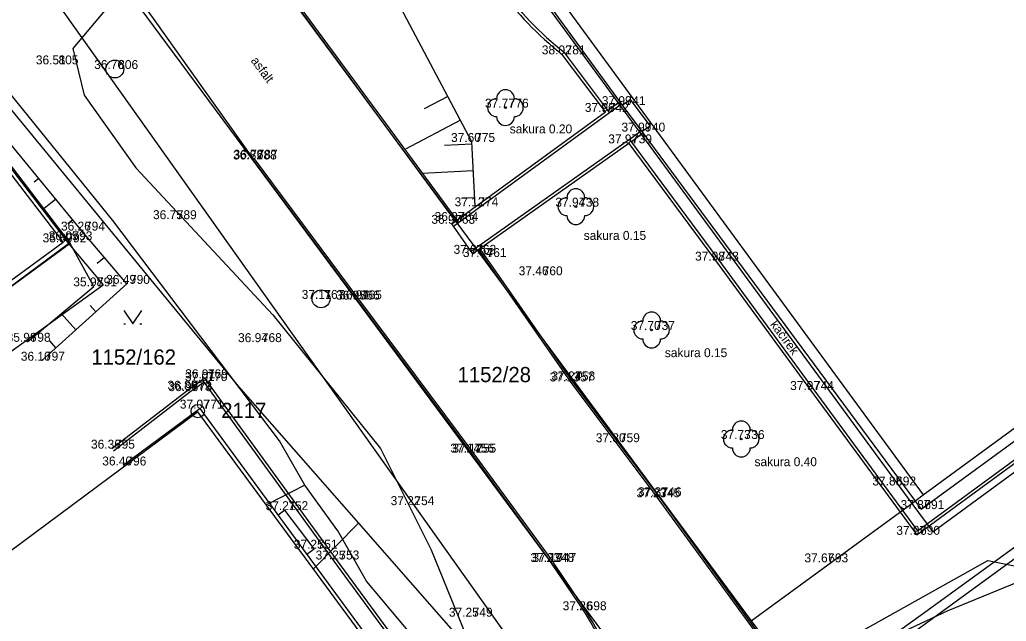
# Model space of a CAD drawing. Extents: x -609709 to -609357, y -1051535 to -1051131.
# Drawn here: x -609623.05 to -609595.44, y -1051300.14 to -1051283.31 of the extents above; entities that cross this region are included whole.
import ezdxf

# ---------------------------------------------------------------- set-up
doc = ezdxf.new("R2010")
doc.units = 0
for name, color, linetype in [('Vrstva 1', 7, 'Continuous'), ('Vrstva 10', 7, 'Continuous'), ('Vrstva 12', 7, 'Continuous'), ('Vrstva 15', 7, 'Continuous'), ('Vrstva 19', 7, 'Continuous'), ('Vrstva 2', 7, 'Continuous'), ('Vrstva 3', 7, 'Continuous'), ('Vrstva 4', 7, 'Continuous'), ('Vrstva 5', 7, 'Continuous'), ('Vrstva 6', 7, 'Continuous'), ('Vrstva 7', 7, 'Continuous'), ('Vrstva 8', 7, 'Continuous'), ('Vrstva 9', 7, 'Continuous')]:
    doc.layers.add(name, color=color, linetype=linetype)

msp = doc.modelspace()

# ---------------------------------------------------------------- linework, layer by layer
at = {"layer": 'Vrstva 1'}
for p, q in [((-609607.87, -1051284.28), (-609607.87, -1051284.28)), ((-609622.06, -1051284.56), (-609622.06, -1051284.56)), ((-609620.39, -1051284.69), (-609620.39, -1051284.69)), ((-609609.46, -1051285.77), (-609609.46, -1051285.77)), ((-609606.66, -1051285.89), (-609606.66, -1051285.89)), ((-609606.19, -1051285.7), (-609606.19, -1051285.7)), ((-609605.64, -1051286.44), (-609605.64, -1051286.44)), ((-609610.4, -1051286.73), (-609610.4, -1051286.73)), ((-609606.01, -1051286.77), (-609606.01, -1051286.77)), ((-609616.51, -1051287.22), (-609616.51, -1051287.22)), ((-609616.49, -1051287.2), (-609616.49, -1051287.2)), ((-609610.31, -1051288.53), (-609610.31, -1051288.53)), ((-609607.49, -1051288.54), (-609607.49, -1051288.54)), ((-609618.75, -1051288.89), (-609618.75, -1051288.89)), ((-609610.87, -1051288.94), (-609610.87, -1051288.94)), ((-609621.32, -1051289.21), (-609621.32, -1051289.21)), ((-609610.96, -1051289.02), (-609610.96, -1051289.02)), ((-609621.84, -1051289.54), (-609621.84, -1051289.54)), ((-609621.67, -1051289.48), (-609621.67, -1051289.48)), ((-609610.37, -1051289.86), (-609610.37, -1051289.86)), ((-609610.08, -1051289.95), (-609610.08, -1051289.95)), ((-609603.58, -1051290.05), (-609603.58, -1051290.05)), ((-609608.51, -1051290.46), (-609608.51, -1051290.46)), ((-609620.98, -1051290.77), (-609620.98, -1051290.77)), ((-609620.06, -1051290.7), (-609620.06, -1051290.7)), ((-609614.62, -1051291.12), (-609614.62, -1051291.12)), ((-609613.63, -1051291.14), (-609613.63, -1051291.14)), ((-609613.57, -1051291.13), (-609613.57, -1051291.13)), ((-609605.37, -1051291.99), (-609605.37, -1051291.99)), ((-609622.84, -1051292.32), (-609622.84, -1051292.32)), ((-609616.37, -1051292.33), (-609616.37, -1051292.33)), ((-609622.44, -1051292.85), (-609622.44, -1051292.85)), ((-609617.89, -1051293.42), (-609617.89, -1051293.42)), ((-609617.88, -1051293.34), (-609617.88, -1051293.34)), ((-609607.6, -1051293.4), (-609607.6, -1051293.4)), ((-609618.34, -1051293.66), (-609618.34, -1051293.66)), ((-609618.32, -1051293.7), (-609618.32, -1051293.7)), ((-609607.65, -1051293.43), (-609607.65, -1051293.43)), ((-609600.92, -1051293.67), (-609600.92, -1051293.67)), ((-609618, -1051294.19), (-609618, -1051294.19)), ((-609602.86, -1051295.04), (-609602.86, -1051295.04)), ((-609620.48, -1051295.31), (-609620.48, -1051295.31)), ((-609606.35, -1051295.13), (-609606.35, -1051295.13)), ((-609610.43, -1051295.42), (-609610.43, -1051295.42)), ((-609610.37, -1051295.42), (-609610.37, -1051295.42)), ((-609620.16, -1051295.78), (-609620.16, -1051295.78)), ((-609598.62, -1051296.34), (-609598.62, -1051296.34)), ((-609605.22, -1051296.67), (-609605.22, -1051296.67)), ((-609605.18, -1051296.64), (-609605.18, -1051296.64)), ((-609612.1, -1051296.89), (-609612.1, -1051296.89)), ((-609597.83, -1051297), (-609597.83, -1051297)), ((-609615.63, -1051297.03), (-609615.63, -1051297.03)), ((-609597.95, -1051297.72), (-609597.95, -1051297.72)), ((-609614.81, -1051298.11), (-609614.81, -1051298.11)), ((-609614.2, -1051298.41), (-609614.2, -1051298.41)), ((-609608.19, -1051298.48), (-609608.19, -1051298.48)), ((-609608.13, -1051298.48), (-609608.13, -1051298.48)), ((-609600.52, -1051298.49), (-609600.52, -1051298.49)), ((-609610.47, -1051300.01), (-609610.47, -1051300.01)), ((-609607.28, -1051299.83), (-609607.28, -1051299.83))]:
    msp.add_line(p, q, dxfattribs=at)
at = {"layer": 'Vrstva 10'}
for p, q in [((-609622.18, -1051273.63), (-609602.58, -1051300.13)), ((-609613.41, -1051275.95), (-609598.09, -1051296.84)), ((-609612.49, -1051276.52), (-609597.77, -1051296.6)), ((-609623.67, -1051277.61), (-609605.63, -1051301.94)), ((-609626.47, -1051283.34), (-609621.69, -1051289.57)), ((-609672.03, -1051326.83), (-609621.69, -1051289.57)), ((-609621.69, -1051289.57), (-609620.72, -1051290.73)), ((-609627.08, -1051295.32), (-609620.72, -1051290.73)), ((-609620.14, -1051291.445), (-609619.89, -1051291.82)), ((-609619.89, -1051291.82), (-609619.64, -1051291.445)), ((-609620.14, -1051291.82), (-609620.09, -1051291.82)), ((-609619.69, -1051291.82), (-609619.64, -1051291.82)), ((-609597.77, -1051296.6), (-609591.61, -1051292.08)), ((-609597.5, -1051297.64), (-609591.01, -1051292.88)), ((-609623.84, -1051298.56), (-609618.08, -1051294.28)), ((-609618.08, -1051294.28), (-609611.31, -1051303.47)), ((-609598.09, -1051296.84), (-609597.77, -1051296.6)), ((-609602.58, -1051300.13), (-609598.09, -1051296.84)), ((-609598.09, -1051296.84), (-609597.5, -1051297.64)), ((-609602.58, -1051300.13), (-609598.83, -1051305.19))]:
    msp.add_line(p, q, dxfattribs=at)
for radius in [0.188, 0.0025]:
    msp.add_circle((-609618.07, -1051294.26), radius, dxfattribs=at)
at = {"layer": 'Vrstva 12'}
for points in [[(-609617.53, -1051308.92), (-609614.08, -1051306.67), (-609612.94, -1051305.52), (-609610.39, -1051304.93), (-609608.61, -1051303.76), (-609606.06, -1051302.68), (-609604.05, -1051302.21), (-609601.38, -1051301.86), (-609597.07, -1051299.84), (-609592.58, -1051298), (-609588.06, -1051296.22), (-609585.76, -1051295.02), (-609575.12, -1051289.04), (-609565.28, -1051281.43), (-609560.89, -1051277.53), (-609555.76, -1051273.58), (-609560.56, -1051267.09), (-609566.32, -1051260.26), (-609571.84, -1051253.12), (-609574.91, -1051248.7), (-609573.88, -1051248.47), (-609573.078, -1051248.47)], [(-609644.336, -1051251.436), (-609604.801, -1051307.048), (-609620.698, -1051318.606), (-609619.426, -1051320.272)], [(-609598.88, -1051264.1), (-609604.42, -1051268.47), (-609611.68, -1051274.04), (-609616.21, -1051277.75), (-609621.57, -1051284.12), (-609621.25, -1051285.42), (-609619.8, -1051287.45), (-609615.97, -1051291.57), (-609612.96, -1051295.31), (-609611.54, -1051298.14), (-609609.99, -1051301.94), (-609609.26, -1051303.04), (-609608.61, -1051303.76)]]:
    msp.add_lwpolyline(points, dxfattribs=at)
at = {"layer": 'Vrstva 15'}
for points in [[(-609592.54, -1051249), (-609597.09, -1051253.54), (-609603.86, -1051260.31), (-609608.84, -1051264.59), (-609616.08, -1051271.44), (-609620.11, -1051274.18), (-609621.01, -1051275.83), (-609623.48, -1051278.12), (-609624.89, -1051278.61), (-609626.41, -1051281.76), (-609625.78, -1051282.81), (-609616.94, -1051293.56), (-609613.57, -1051297.39), (-609614.852, -1051298.693)], [(-609615.07, -1051296.33), (-609615.78, -1051295.09), (-609620.45, -1051288.93), (-609623.66, -1051284.97), (-609624.82, -1051283.57), (-609624.94, -1051283.19), (-609624.89, -1051282.73), (-609624.27, -1051280.91), (-609623.86, -1051279.98), (-609623.26, -1051279.09), (-609620.52, -1051275.54), (-609620, -1051274.23), (-609619.55, -1051273.31), (-609618.56, -1051272.15), (-609610.34, -1051264.5)], [(-609590.03, -1051312.18), (-609589.76, -1051311.7), (-609589.53, -1051310.88), (-609589.67, -1051309.74), (-609590.15, -1051307.96), (-609591.04, -1051306.42), (-609592.5, -1051304.31), (-609593.89, -1051302.67), (-609595.04, -1051301.8), (-609596.35, -1051301.28), (-609597.56, -1051301.3), (-609599.65, -1051302.04), (-609600.19, -1051302.19), (-609606.15, -1051303.02), (-609606.65, -1051303), (-609609.43, -1051302.64), (-609610.87, -1051301.83), (-609612.03, -1051300.58), (-609613.35, -1051299.02), (-609614.15, -1051297.61), (-609615.07, -1051296.33), (-609616.17, -1051296.89)], [(-609613.57, -1051297.39), (-609610.53, -1051300.86), (-609606.14, -1051302.33), (-609601.51, -1051301.54), (-609595.96, -1051298.44), (-609593.36, -1051298.96), (-609591.48, -1051303.13), (-609590.4, -1051306.74), (-609588.91, -1051310.41), (-609588.82, -1051311.77), (-609588.19, -1051312.627)]]:
    msp.add_lwpolyline(points, dxfattribs=at)
at = {"layer": 'Vrstva 19'}
for points in [[(-609589.68, -1051320.38), (-609591.1, -1051321.45), (-609591.26, -1051321.42), (-609595.66, -1051315.54), (-609599.29, -1051310.59), (-609603.57, -1051304.6), (-609603.53, -1051304.45), (-609597.5, -1051300.05), (-609589.44, -1051294.18), (-609579.1, -1051286.55), (-609565.69, -1051276.62), (-609561.84, -1051273.9), (-609561.08, -1051273.38), (-609561.07, -1051273.26), (-609565.31, -1051267.81), (-609569, -1051263.05), (-609568.98, -1051262.9), (-609566.12, -1051260.7)], [(-609561.81, -1051273.58), (-609564.02, -1051275.2), (-609565.73, -1051276.44), (-609579.25, -1051286.33), (-609589.6, -1051294), (-609597.83, -1051299.97), (-609603.9, -1051304.33), (-609603.93, -1051304.5), (-609599.56, -1051310.67), (-609595.87, -1051315.71), (-609591.35, -1051321.78), (-609591.2, -1051321.8), (-609589.56, -1051320.54)]]:
    msp.add_lwpolyline(points, dxfattribs=at)
at = {"layer": 'Vrstva 4'}
for p, q in [((-609606.547, -1051285.907), (-609607.812, -1051284.224)), ((-609606.595, -1051285.843), (-609606.263, -1051285.6)), ((-609610.914, -1051289.085), (-609606.547, -1051285.907)), ((-609605.945, -1051286.724), (-609605.612, -1051286.478)), ((-609605.992, -1051286.659), (-609603.516, -1051290.003)), ((-609603.516, -1051290.003), (-609600.856, -1051293.623)), ((-609618.293, -1051293.725), (-609617.899, -1051293.45)), ((-609617.899, -1051293.45), (-609614.265, -1051298.457)), ((-609620.431, -1051295.373), (-609618.293, -1051293.725)), ((-609614.265, -1051298.457), (-609612.274, -1051301.157)), ((-609607.238, -1051299.802), (-609608.129, -1051298.482))]:
    msp.add_line(p, q, dxfattribs=at)
for points in [[(-609621.637, -1051274.354), (-609619.32, -1051277.58), (-609616.81, -1051280.78), (-609610.823, -1051288.92)], [(-609621.68, -1051274.38), (-609619.36, -1051277.61), (-609616.85, -1051280.81), (-609610.863, -1051288.949)], [(-609622.489, -1051279.091), (-609621.87, -1051279.77), (-609619.32, -1051283.28), (-609616.512, -1051287.217)], [(-609626.358, -1051283.486), (-609626.47, -1051283.57), (-609624.29, -1051286.35), (-609621.84, -1051289.54), (-609624.11, -1051291.2)], [(-609626.358, -1051283.486), (-609624.179, -1051286.264), (-609621.642, -1051289.568), (-609624.027, -1051291.313)], [(-609606.66, -1051285.89), (-609607.87, -1051284.28)], [(-609606.547, -1051285.907), (-609606.216, -1051285.665)], [(-609610.96, -1051289.02), (-609606.66, -1051285.89)], [(-609605.992, -1051286.659), (-609605.66, -1051286.413)], [(-609606.01, -1051286.77), (-609610.37, -1051289.86), (-609610.96, -1051289.02)], [(-609605.992, -1051286.659), (-609610.416, -1051289.795)], [(-609606.01, -1051286.77), (-609603.58, -1051290.05), (-609600.92, -1051293.67), (-609597.95, -1051297.72), (-609593.94, -1051294.78)], [(-609616.53, -1051287.23), (-609616.49, -1051287.2)], [(-609616.53, -1051287.23), (-609613.61, -1051291.16), (-609610.41, -1051295.45), (-609608.17, -1051298.51)], [(-609616.49, -1051287.2), (-609613.57, -1051291.13), (-609610.37, -1051295.42), (-609608.13, -1051298.48)], [(-609622.84, -1051292.32), (-609620.98, -1051290.77), (-609621.642, -1051289.568)], [(-609610.218, -1051289.752), (-609607.65, -1051293.43), (-609605.22, -1051296.67), (-609602.5, -1051300.4), (-609600.14, -1051303.56), (-609598.95, -1051305.13)], [(-609610.177, -1051289.724), (-609607.609, -1051293.401), (-609605.18, -1051296.64), (-609602.46, -1051300.37), (-609600.1, -1051303.53), (-609598.913, -1051305.096)], [(-609620.48, -1051295.31), (-609618.34, -1051293.66), (-609617.88, -1051293.34), (-609614.2, -1051298.41), (-609612.21, -1051301.11), (-609610.43, -1051303.53), (-609613.983, -1051306.145)], [(-609600.855, -1051293.623), (-609597.933, -1051297.608), (-609593.987, -1051294.715)], [(-609607.28, -1051299.83), (-609608.17, -1051298.51)]]:
    msp.add_lwpolyline(points, dxfattribs=at)
for centre, radius, start, end in [((-609602.176, -1051277.026), 9.222, 199.6719, 231.8723), ((-609602.176, -1051277.026), 9.142, 199.5981, 231.9379), ((-609614.056, -1051304.232), 8.081, 11.2198, 33.01), ((-609614.056, -1051304.232), 8.131, 11.2294, 33.013)]:
    msp.add_arc(centre, radius, start, end, dxfattribs=at)
at = {"layer": 'Vrstva 5'}
for centre in [(-609620.39, -1051284.69), (-609614.62, -1051291.12)]:
    msp.add_circle(centre, 0.25, dxfattribs=at)
at = {"layer": 'Vrstva 6'}
for points in [[(-609610.31, -1051288.53), (-609610.4, -1051286.73), (-609612.71, -1051282.35), (-609615.84, -1051278.39), (-609617.55, -1051275.92), (-609615.49, -1051274.55), (-609612.49, -1051270.95), (-609610.45, -1051268.68), (-609607.94, -1051265.3), (-609606.28, -1051264.06), (-609602.59, -1051259.95), (-609593.93, -1051248.07), (-609590.64, -1051244.54), (-609589.23, -1051241.892)], [(-609622.44, -1051292.85), (-609620.06, -1051290.7), (-609621.32, -1051289.21), (-609623.89, -1051286.09), (-609626.35, -1051283.48)]]:
    msp.add_lwpolyline(points, dxfattribs=at)
at = {"layer": 'Vrstva 7'}
for centre in [(-609609.46, -1051285.77), (-609607.49, -1051288.54), (-609605.37, -1051291.99), (-609602.86, -1051295.04)]:
    msp.add_circle(centre, 0.025, dxfattribs=at)
for centre, start, end in [((-609609.46, -1051285.52), 0, 180), ((-609609.71, -1051285.77), 90, 270), ((-609609.21, -1051285.77), 270, 90), ((-609609.46, -1051286.02), 180, 0), ((-609607.49, -1051288.29), 0, 180), ((-609607.74, -1051288.54), 90, 270), ((-609607.24, -1051288.54), 270, 90), ((-609607.49, -1051288.79), 180, 0), ((-609605.37, -1051291.74), 0, 180), ((-609605.62, -1051291.99), 90, 270), ((-609605.12, -1051291.99), 270, 90), ((-609605.37, -1051292.24), 180, 0), ((-609603.11, -1051295.04), 90, 270), ((-609602.86, -1051294.79), 0, 180), ((-609602.61, -1051295.04), 270, 90), ((-609602.86, -1051295.29), 180, 0)]:
    msp.add_arc(centre, 0.25, start, end, dxfattribs=at)
at = {"layer": 'Vrstva 8'}
for p, q in [((-609611.071, -1051285.458), (-609611.733, -1051285.808)), ((-609610.721, -1051286.122), (-609612.277, -1051286.942)), ((-609610.397, -1051286.792), (-609611.165, -1051286.831)), ((-609610.359, -1051287.541), (-609611.784, -1051287.612)), ((-609622.523, -1051287.75), (-609622.649, -1051287.854)), ((-609622.046, -1051288.329), (-609622.381, -1051288.605)), ((-609610.322, -1051288.29), (-609610.694, -1051288.309)), ((-609621.569, -1051288.908), (-609621.711, -1051289.025)), ((-609620.683, -1051289.963), (-609620.885, -1051290.134)), ((-609620.927, -1051291.483), (-609621.083, -1051291.31)), ((-609621.483, -1051291.986), (-609621.894, -1051291.532)), ((-609622.04, -1051292.489), (-609622.212, -1051292.298))]:
    msp.add_line(p, q, dxfattribs=at)
at = {"layer": 'Vrstva 9'}
for points in [[(-609612.85, -1051276.57), (-609606.19, -1051285.7)], [(-609606.19, -1051285.7), (-609605.973, -1051285.539)], [(-609605.973, -1051285.539), (-609605.423, -1051286.279)], [(-609606.19, -1051285.7), (-609605.64, -1051286.44)], [(-609605.64, -1051286.44), (-609605.423, -1051286.279)], [(-609605.64, -1051286.44), (-609597.83, -1051297)], [(-609597.83, -1051297), (-609590.33, -1051291.53)], [(-609614.69, -1051305.99), (-609611.23, -1051303.42), (-609618, -1051294.19), (-609620.16, -1051295.78)], [(-609615.015, -1051298.26), (-609614.81, -1051298.11), (-609615.63, -1051297.03), (-609615.817, -1051297.167)]]:
    msp.add_lwpolyline(points, dxfattribs=at)

# ---------------------------------------------------------------- texts
at = {"layer": 'Vrstva 10'}
for s, p in [('1152/162', (-609621.05, -1051292.96)), ('1152/28', (-609610.8, -1051293.45)), ('2117', (-609617.415, -1051294.452))]:
    msp.add_text(s, height=0.425, dxfattribs=at).set_placement(p)
at = {"layer": 'Vrstva 2'}
for s, p in [(' 781', (-609607.87, -1051284.28)), (' 805', (-609622.06, -1051284.56)), (' 806', (-609620.39, -1051284.69)), (' 776', (-609609.46, -1051285.77)), (' 742', (-609606.66, -1051285.89)), (' 741', (-609606.19, -1051285.7)), (' 740', (-609605.64, -1051286.44)), (' 775', (-609610.4, -1051286.73)), (' 739', (-609606.01, -1051286.77)), (' 788', (-609616.51, -1051287.22)), (' 787', (-609616.49, -1051287.2)), (' 774', (-609610.31, -1051288.53)), (' 738', (-609607.49, -1051288.54)), (' 789', (-609618.75, -1051288.89)), (' 764', (-609610.87, -1051288.94)), (' 794', (-609621.32, -1051289.21)), (' 763', (-609610.96, -1051289.02)), (' 792', (-609621.84, -1051289.54)), (' 793', (-609621.67, -1051289.48)), (' 762', (-609610.37, -1051289.86)), (' 761', (-609610.08, -1051289.95)), (' 743', (-609603.58, -1051290.05)), (' 760', (-609608.51, -1051290.46)), (' 791', (-609620.98, -1051290.77)), (' 790', (-609620.06, -1051290.7)), (' 767', (-609614.62, -1051291.12)), (' 766', (-609613.63, -1051291.14)), (' 765', (-609613.57, -1051291.13)), (' 737', (-609605.37, -1051291.99)), (' 798', (-609622.84, -1051292.32)), (' 768', (-609616.37, -1051292.33)), (' 797', (-609622.44, -1051292.85)), (' 769', (-609617.88, -1051293.34)), (' 758', (-609607.6, -1051293.4)), (' 772', (-609618.34, -1051293.66)), (' 770', (-609617.89, -1051293.42)), (' 757', (-609607.65, -1051293.43)), (' 744', (-609600.92, -1051293.67)), (' 773', (-609618.32, -1051293.7)), (' 771', (-609618, -1051294.19)), (' 736', (-609602.86, -1051295.04)), (' 795', (-609620.48, -1051295.31)), (' 759', (-609606.35, -1051295.13)), (' 756', (-609610.43, -1051295.42)), (' 755', (-609610.37, -1051295.42)), (' 796', (-609620.16, -1051295.78)), (' 692', (-609598.62, -1051296.34)), (' 745', (-609605.22, -1051296.67)), (' 746', (-609605.18, -1051296.64)), (' 754', (-609612.1, -1051296.89)), (' 752', (-609615.63, -1051297.03)), (' 691', (-609597.83, -1051297)), (' 690', (-609597.95, -1051297.72)), (' 751', (-609614.81, -1051298.11)), (' 753', (-609614.2, -1051298.41)), (' 748', (-609608.19, -1051298.48)), (' 747', (-609608.13, -1051298.48)), (' 693', (-609600.52, -1051298.49)), (' 749', (-609610.47, -1051300.01)), (' 698', (-609607.28, -1051299.83))]:
    msp.add_text(s, height=0.25, dxfattribs=at).set_placement(p)
at = {"layer": 'Vrstva 3'}
for s, p in [('38.02', (-609608.443, -1051284.28)), ('36.51', (-609622.602, -1051284.56)), ('36.76', (-609620.969, -1051284.69)), ('37.77', (-609610.033, -1051285.77)), ('37.96', (-609607.239, -1051285.89)), ('37.99', (-609606.763, -1051285.7)), ('37.99', (-609606.213, -1051286.44)), ('37.60', (-609610.983, -1051286.73)), ('37.97', (-609606.583, -1051286.77)), ('36.82', (-609617.083, -1051287.22)), ('36.76', (-609617.069, -1051287.2)), ('37.12', (-609610.883, -1051288.53)), ('37.94', (-609608.063, -1051288.54)), ('36.75', (-609619.323, -1051288.89)), ('36.97', (-609611.443, -1051288.94)), ('36.26', (-609621.899, -1051289.21)), ('36.97', (-609611.533, -1051289.02)), ('35.89', (-609622.413, -1051289.54)), ('36.05', (-609622.243, -1051289.48)), ('37.01', (-609610.912, -1051289.86)), ('37.04', (-609610.653, -1051289.95)), ('37.98', (-609604.153, -1051290.05)), ('37.46', (-609609.089, -1051290.46)), ('35.98', (-609621.553, -1051290.77)), ('36.49', (-609620.633, -1051290.7)), ('37.11', (-609615.162, -1051291.12)), ('36.95', (-609614.203, -1051291.14)), ('36.91', (-609614.112, -1051291.13)), ('37.70', (-609605.953, -1051291.99)), ('35.96', (-609623.419, -1051292.32)), ('36.94', (-609616.943, -1051292.33)), ('36.10', (-609623.023, -1051292.85)), ('36.91', (-609618.422, -1051293.34)), ('37.24', (-609608.173, -1051293.4)), ('36.86', (-609618.919, -1051293.66)), ('37.01', (-609618.432, -1051293.42)), ('37.13', (-609608.223, -1051293.43)), ('37.97', (-609601.493, -1051293.67)), ('36.98', (-609618.893, -1051293.7)), ('37.07', (-609618.573, -1051294.19)), ('37.73', (-609603.433, -1051295.04)), ('36.36', (-609621.059, -1051295.31)), ('37.30', (-609606.933, -1051295.13)), ('37.14', (-609611.003, -1051295.42)), ('37.12', (-609610.943, -1051295.42)), ('36.40', (-609620.743, -1051295.78)), ('37.88', (-609599.193, -1051296.34)), ('37.23', (-609605.793, -1051296.67)), ('37.37', (-609605.753, -1051296.64)), ('37.22', (-609612.673, -1051296.89)), ('37.21', (-609616.172, -1051297.03)), ('37.87', (-609598.403, -1051297)), ('37.97', (-609598.523, -1051297.72)), ('37.25', (-609615.383, -1051298.11)), ('37.25', (-609614.773, -1051298.41)), ('37.23', (-609608.763, -1051298.48)), ('37.19', (-609608.703, -1051298.48)), ('37.67', (-609601.093, -1051298.49)), ('37.25', (-609611.043, -1051300.01)), ('37.26', (-609607.859, -1051299.83))]:
    msp.add_text(s, height=0.25, dxfattribs=at).set_placement(p)
at = {"layer": 'Vrstva 4'}
msp.add_text('asfalt', height=0.25, rotation=306.5559, dxfattribs=at).set_placement((-609616.598, -1051284.46))
at = {"layer": 'Vrstva 5'}
msp.add_text('kačírek', height=0.25, rotation=306.3087, dxfattribs=at).set_placement((-609602.065, -1051291.84))
at = {"layer": 'Vrstva 7'}
for s, p in [('sakura 0.20', (-609609.34, -1051286.49)), ('sakura 0.15', (-609607.27, -1051289.47)), ('sakura 0.15', (-609605, -1051292.75)), ('sakura 0.40', (-609602.49, -1051295.8))]:
    msp.add_text(s, height=0.25, dxfattribs=at).set_placement(p)

doc.saveas('drawing.dxf')
